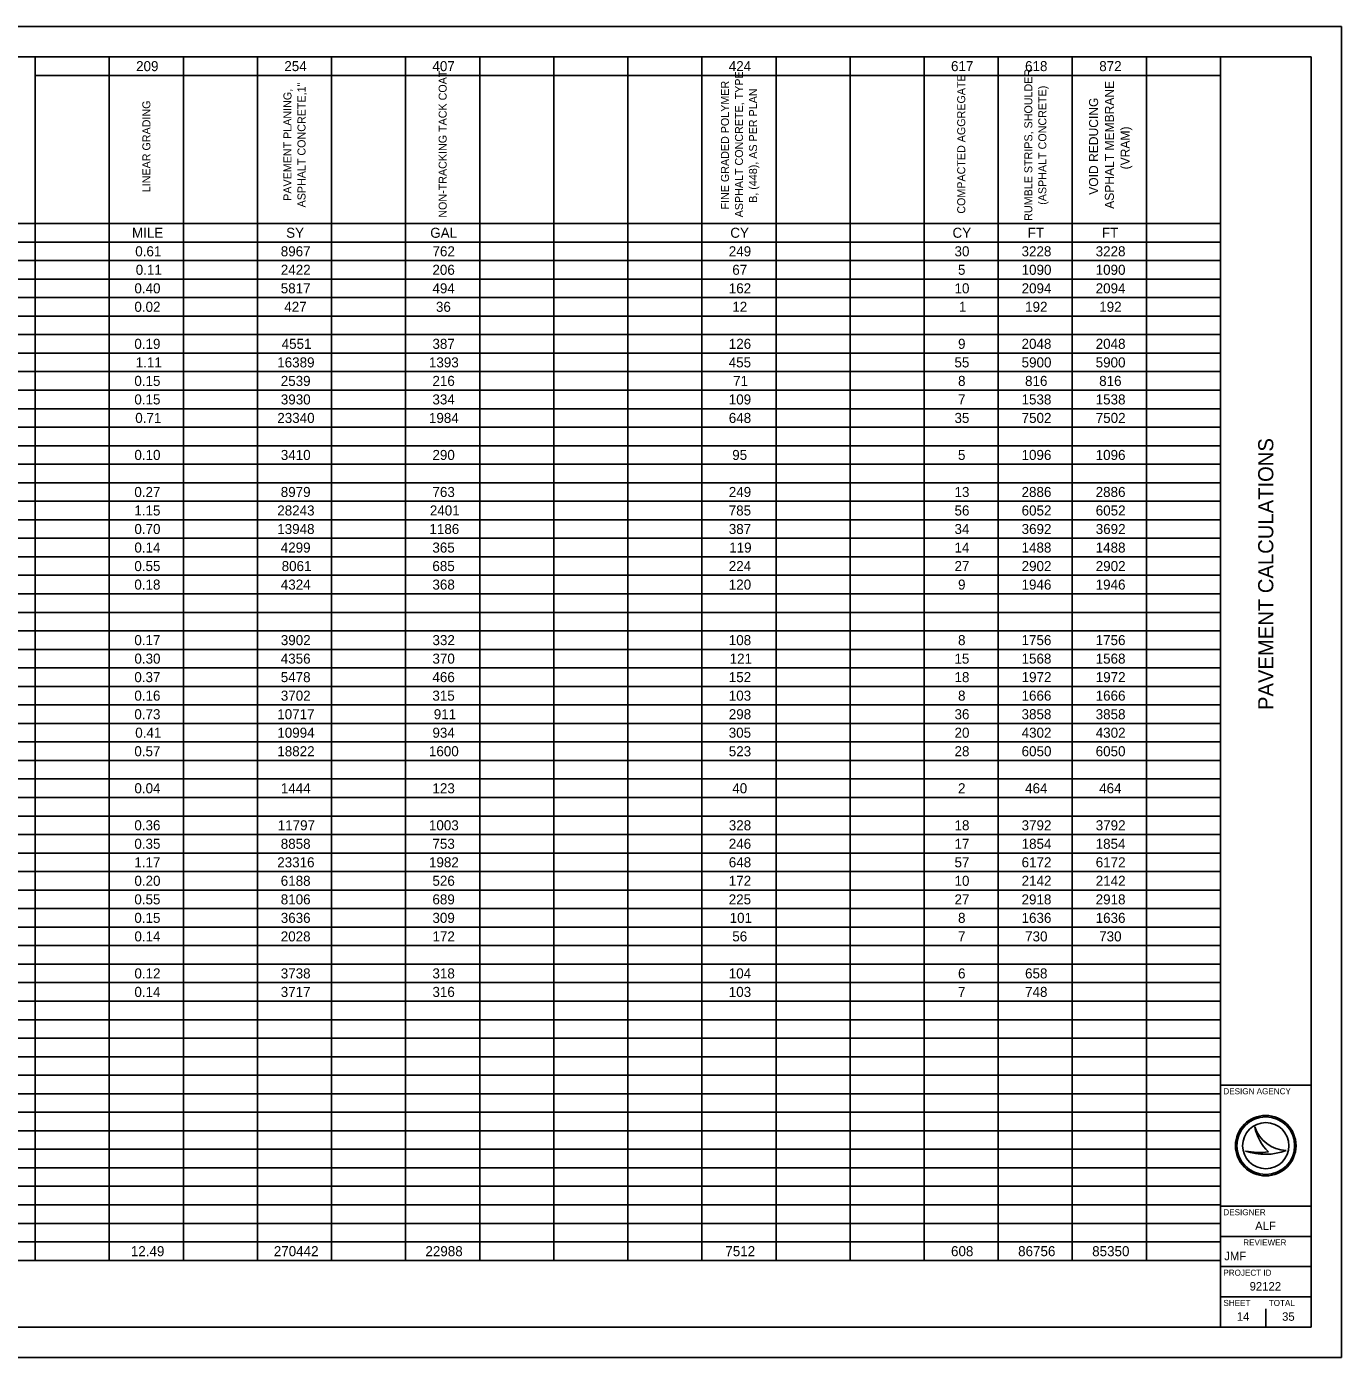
# Model space of a CAD drawing. Extents: x 0 to 34, y 0 to 22.
# Drawn here: x 12.27 to 34, y 0 to 22 of the extents above; entities that cross this region are included whole.
import ezdxf

# ---------------------------------------------------------------- set-up
doc = ezdxf.new("R2010")
doc.units = 0
for name, color, linetype in [('Default', 7, 'Continuous'), ('SH_Border', 7, 'Continuous'), ('SH_Cut_Line', 7, 'Continuous'), ('SH_Data', 7, 'Continuous')]:
    doc.layers.add(name, color=color, linetype=linetype)

msp = doc.modelspace()

# ---------------------------------------------------------------- linework, layer by layer
at = {"layer": 'Default'}
for p, q in [((1.5, 21.5), (32.002, 21.5)), ((12.412, 21.5), (12.412, 1.603)), ((13.636, 21.5), (13.636, 1.603)), ((14.861, 21.5), (14.861, 1.603)), ((16.085, 21.5), (16.085, 1.603)), ((17.309, 21.5), (17.309, 1.603)), ((18.534, 21.5), (18.534, 1.603)), ((19.758, 21.5), (19.758, 1.603)), ((20.983, 21.5), (20.983, 1.603)), ((22.207, 21.5), (22.207, 1.603)), ((23.431, 21.5), (23.431, 1.603)), ((24.656, 21.5), (24.656, 1.603)), ((25.88, 21.5), (25.88, 1.603)), ((27.105, 21.5), (27.105, 1.603)), ((28.329, 21.5), (28.329, 1.603)), ((29.553, 21.5), (29.553, 1.603)), ((30.778, 21.5), (30.778, 1.603)), ((32.002, 21.5), (32.002, 1.603)), ((12.412, 21.194), (32.002, 21.194)), ((7.514, 18.745), (32.002, 18.745)), ((1.5, 18.439), (32.002, 18.439)), ((1.5, 18.133), (32.002, 18.133)), ((1.5, 17.827), (32.002, 17.827)), ((1.5, 17.521), (32.002, 17.521)), ((1.5, 17.215), (32.002, 17.215)), ((1.5, 16.908), (32.002, 16.908)), ((1.5, 16.602), (32.002, 16.602)), ((1.5, 16.296), (32.002, 16.296)), ((1.5, 15.99), (32.002, 15.99)), ((1.5, 15.684), (32.002, 15.684)), ((1.5, 15.378), (32.002, 15.378)), ((1.5, 15.072), (32.002, 15.072)), ((1.5, 14.766), (32.002, 14.766)), ((1.5, 14.46), (32.002, 14.46)), ((1.5, 14.154), (32.002, 14.154)), ((1.5, 13.847), (32.002, 13.847)), ((1.5, 13.541), (32.002, 13.541)), ((1.5, 13.235), (32.002, 13.235)), ((1.5, 12.929), (32.002, 12.929)), ((1.5, 12.623), (32.002, 12.623)), ((1.5, 12.317), (32.002, 12.317)), ((1.5, 12.011), (32.002, 12.011)), ((1.5, 11.705), (32.002, 11.705)), ((1.5, 11.399), (32.002, 11.399)), ((1.5, 11.092), (32.002, 11.092)), ((1.5, 10.786), (32.002, 10.786)), ((1.5, 10.48), (32.002, 10.48)), ((1.5, 10.174), (32.002, 10.174)), ((1.5, 9.868), (32.002, 9.868)), ((1.5, 9.562), (32.002, 9.562)), ((1.5, 9.256), (32.002, 9.256)), ((1.5, 8.95), (32.002, 8.95)), ((1.5, 8.644), (32.002, 8.644)), ((1.5, 8.338), (32.002, 8.338)), ((1.5, 8.031), (32.002, 8.031)), ((1.5, 7.725), (32.002, 7.725)), ((1.5, 7.419), (32.002, 7.419)), ((1.5, 7.113), (32.002, 7.113)), ((1.5, 6.807), (32.002, 6.807)), ((1.5, 6.501), (32.002, 6.501)), ((1.5, 6.195), (32.002, 6.195)), ((1.5, 5.889), (32.002, 5.889)), ((1.5, 5.583), (32.002, 5.583)), ((1.5, 5.277), (32.002, 5.277)), ((1.5, 4.97), (32.002, 4.97)), ((1.5, 4.664), (32.002, 4.664)), ((1.5, 4.358), (32.002, 4.358)), ((1.5, 4.052), (32.002, 4.052)), ((1.5, 3.746), (32.002, 3.746)), ((1.5, 3.44), (32.002, 3.44)), ((1.5, 3.134), (32.002, 3.134)), ((1.5, 2.828), (32.002, 2.828)), ((1.5, 2.522), (32.002, 2.522)), ((1.5, 2.215), (32.002, 2.215)), ((1.5, 1.909), (32.002, 1.909)), ((1.5, 1.603), (32.002, 1.603))]:
    msp.add_line(p, q, dxfattribs=at)
at = {"layer": 'SH_Border'}
for p, q in [((32, 0.5), (32, 21.5)), ((32, 4.5), (33.5, 4.5)), ((32, 2.5), (33.5, 2.5)), ((32, 2), (33.5, 2)), ((32, 1.5), (33.5, 1.5)), ((32, 1), (33.5, 1))]:
    msp.add_line(p, q, dxfattribs=at)
msp.add_lwpolyline([(1.5, 21.5), (33.5, 21.5), (33.5, 0.5), (1.5, 0.5)], close=True, dxfattribs=at)
at = {"layer": 'SH_Cut_Line'}
msp.add_lwpolyline([(0, 0), (34, 0), (34, 22), (0, 22)], close=True, dxfattribs=at)
at = {"layer": 'SH_Data'}
for p, q in [((32.567, 3.81), (32.567, 3.81)), ((32.417, 3.41), (32.417, 3.41)), ((32.75, 3.5), (32.75, 3.5)), ((33.087, 3.419), (33.087, 3.419)), ((32.375, 0.675), (32.375, 0.675)), ((32.75, 0.5), (32.75, 0.8))]:
    msp.add_line(p, q, dxfattribs=at)
for radius in [0.5, 0.477, 0.477, 0.382]:
    msp.add_circle((32.75, 3.5), radius, dxfattribs=at)
for centre, radius, start, end in [((33.116, 3.998), 0.58, 198.9257, 198.9319), ((33.347, 3.97), 0.796, 191.6379, 191.6421), ((33.116, 3.998), 0.58, 198.9319, 267.1657), ((33.347, 3.97), 0.796, 191.6421, 226.0947), ((32.739, 4.37), 1.013, 251.4576, 290.0832), ((32.648, 4.654), 1.266, 259.4964, 259.4995), ((32.739, 4.37), 1.013, 251.4527, 251.4576), ((32.648, 4.654), 1.266, 259.4995, 276.6672)]:
    msp.add_arc(centre, radius, start, end, dxfattribs=at)

# ---------------------------------------------------------------- texts
at = {"layer": 'Default'}
for s, height, p in [('209', 0.1657, (14.079, 21.264)), ('254', 0.1657, (16.529, 21.264)), ('407', 0.1657, (18.977, 21.264)), ('424', 0.1657, (23.875, 21.264)), ('617', 0.1657, (27.548, 21.264)), ('618', 0.1657, (28.772, 21.264)), ('872', 0.1657, (29.998, 21.264)), ('MILE', 0.1657, (14.011, 18.509)), ('SY', 0.1657, (16.559, 18.509)), ('GAL', 0.1657, (18.941, 18.509)), ('CY', 0.1657, (23.9, 18.509)), ('CY', 0.1657, (27.573, 18.509)), ('FT', 0.1657, (28.816, 18.509)), ('FT', 0.1657, (30.041, 18.509)), ('0.61', 0.1657, (14.065, 18.203)), ('8967', 0.1657, (16.47, 18.203)), ('762', 0.1657, (18.978, 18.203)), ('249', 0.1657, (23.875, 18.203)), ('30', 0.1657, (27.606, 18.203)), ('3228', 0.1657, (28.714, 18.203)), ('3228', 0.1657, (29.939, 18.203)), ('0.11', 0.1657, (14.073, 17.897)), ('2422', 0.1657, (16.471, 17.897)), ('206', 0.1657, (18.977, 17.897)), ('67', 0.1657, (23.933, 17.897)), ('5', 0.166, (27.663, 17.897)), ('1090', 0.1657, (28.715, 17.897)), ('1090', 0.1657, (29.939, 17.897)), ('0.40', 0.1657, (14.051, 17.591)), ('5817', 0.1657, (16.47, 17.591)), ('494', 0.1657, (18.977, 17.591)), ('162', 0.1657, (23.875, 17.591)), ('10', 0.1657, (27.606, 17.591)), ('2094', 0.1657, (28.715, 17.591)), ('2094', 0.1657, (29.939, 17.591)), ('0.02', 0.1657, (14.051, 17.285)), ('427', 0.1657, (16.528, 17.285)), ('36', 0.1657, (19.035, 17.285)), ('12', 0.1657, (23.933, 17.285)), ('1', 0.166, (27.678, 17.285)), ('192', 0.1657, (28.773, 17.285)), ('192', 0.1657, (29.998, 17.285)), ('0.19', 0.1657, (14.05, 16.673)), ('4551', 0.1657, (16.485, 16.673)), ('387', 0.1657, (18.977, 16.673)), ('126', 0.1657, (23.875, 16.673)), ('9', 0.166, (27.664, 16.673)), ('2048', 0.1657, (28.714, 16.673)), ('2048', 0.1657, (29.939, 16.673)), ('1.11', 0.1657, (14.073, 16.366)), ('16389', 0.1657, (16.412, 16.366)), ('1393', 0.1657, (18.919, 16.366)), ('455', 0.1657, (23.874, 16.366)), ('55', 0.1657, (27.605, 16.366)), ('5900', 0.1657, (28.715, 16.366)), ('5900', 0.1657, (29.939, 16.366)), ('0.15', 0.1657, (14.05, 16.06)), ('2539', 0.1657, (16.47, 16.06)), ('216', 0.1657, (18.977, 16.06)), ('71', 0.1657, (23.947, 16.06)), ('8', 0.166, (27.664, 16.06)), ('816', 0.1657, (28.772, 16.06)), ('816', 0.1657, (29.997, 16.06)), ('0.15', 0.1657, (14.05, 15.754)), ('3930', 0.1657, (16.471, 15.754)), ('334', 0.1657, (18.977, 15.754)), ('109', 0.1657, (23.875, 15.754)), ('7', 0.166, (27.664, 15.754)), ('1538', 0.1657, (28.714, 15.754)), ('1538', 0.1657, (29.939, 15.754)), ('0.71', 0.1657, (14.065, 15.448)), ('23340', 0.1657, (16.413, 15.448)), ('1984', 0.1657, (18.919, 15.448)), ('648', 0.1657, (23.875, 15.448)), ('35', 0.1657, (27.605, 15.448)), ('7502', 0.1657, (28.715, 15.448)), ('7502', 0.1657, (29.94, 15.448)), ('0.10', 0.1657, (14.051, 14.836)), ('3410', 0.1657, (16.471, 14.836)), ('290', 0.1657, (18.977, 14.836)), ('95', 0.1657, (23.932, 14.836)), ('5', 0.166, (27.663, 14.836)), ('1096', 0.1657, (28.714, 14.836)), ('1096', 0.1657, (29.939, 14.836)), ('0.27', 0.1657, (14.05, 14.224)), ('8979', 0.1657, (16.47, 14.224)), ('763', 0.1657, (18.977, 14.224)), ('249', 0.1657, (23.875, 14.224)), ('13', 0.1657, (27.606, 14.224)), ('2886', 0.1657, (28.714, 14.224)), ('2886', 0.1657, (29.939, 14.224)), ('1.15', 0.1657, (14.05, 13.918)), ('28243', 0.1657, (16.412, 13.918)), ('2401', 0.1657, (18.934, 13.918)), ('785', 0.1657, (23.874, 13.918)), ('56', 0.1657, (27.606, 13.918)), ('6052', 0.1657, (28.715, 13.918)), ('6052', 0.1657, (29.94, 13.918)), ('0.70', 0.1657, (14.051, 13.612)), ('13948', 0.1657, (16.412, 13.612)), ('1186', 0.1657, (18.927, 13.612)), ('387', 0.1657, (23.875, 13.612)), ('34', 0.1657, (27.606, 13.612)), ('3692', 0.1657, (28.715, 13.612)), ('3692', 0.1657, (29.94, 13.612)), ('0.14', 0.1657, (14.051, 13.305)), ('4299', 0.1657, (16.47, 13.305)), ('365', 0.1657, (18.976, 13.305)), ('119', 0.1657, (23.882, 13.305)), ('14', 0.1657, (27.606, 13.305)), ('1488', 0.1657, (28.714, 13.305)), ('1488', 0.1657, (29.939, 13.305)), ('0.55', 0.1657, (14.05, 12.999)), ('8061', 0.1657, (16.485, 12.999)), ('685', 0.1657, (18.976, 12.999)), ('224', 0.1657, (23.875, 12.999)), ('27', 0.1657, (27.606, 12.999)), ('2902', 0.1657, (28.715, 12.999)), ('2902', 0.1657, (29.94, 12.999)), ('0.18', 0.1657, (14.05, 12.693)), ('4324', 0.1657, (16.471, 12.693)), ('368', 0.1657, (18.977, 12.693)), ('120', 0.1657, (23.875, 12.693)), ('9', 0.166, (27.664, 12.693)), ('1946', 0.1657, (28.714, 12.693)), ('1946', 0.1657, (29.939, 12.693)), ('0.17', 0.1657, (14.05, 11.775)), ('3902', 0.1657, (16.471, 11.775)), ('332', 0.1657, (18.978, 11.775)), ('108', 0.1657, (23.875, 11.775)), ('8', 0.166, (27.664, 11.775)), ('1756', 0.1657, (28.714, 11.775)), ('1756', 0.1657, (29.939, 11.775)), ('0.30', 0.1657, (14.051, 11.469)), ('4356', 0.1657, (16.47, 11.469)), ('370', 0.1657, (18.977, 11.469)), ('121', 0.1657, (23.889, 11.469)), ('15', 0.1657, (27.605, 11.469)), ('1568', 0.1657, (28.714, 11.469)), ('1568', 0.1657, (29.939, 11.469)), ('0.37', 0.1657, (14.05, 11.163)), ('5478', 0.1657, (16.47, 11.163)), ('466', 0.1657, (18.977, 11.163)), ('152', 0.1657, (23.875, 11.163)), ('18', 0.1657, (27.606, 11.163)), ('1972', 0.1657, (28.715, 11.163)), ('1972', 0.1657, (29.94, 11.163)), ('0.16', 0.1657, (14.05, 10.857)), ('3702', 0.1657, (16.471, 10.857)), ('315', 0.1657, (18.976, 10.857)), ('103', 0.1657, (23.875, 10.857)), ('8', 0.166, (27.664, 10.857)), ('1666', 0.1657, (28.714, 10.857)), ('1666', 0.1657, (29.939, 10.857)), ('0.73', 0.1657, (14.05, 10.55)), ('10717', 0.1657, (16.412, 10.55)), ('911', 0.1657, (18.999, 10.55)), ('298', 0.1657, (23.875, 10.55)), ('36', 0.1657, (27.606, 10.55)), ('3858', 0.1657, (28.714, 10.55)), ('3858', 0.1657, (29.939, 10.55)), ('0.41', 0.1657, (14.065, 10.244)), ('10994', 0.1657, (16.413, 10.244)), ('934', 0.1657, (18.977, 10.244)), ('305', 0.1657, (23.874, 10.244)), ('20', 0.1657, (27.606, 10.244)), ('4302', 0.1657, (28.715, 10.244)), ('4302', 0.1657, (29.94, 10.244)), ('0.57', 0.1657, (14.05, 9.938)), ('18822', 0.1657, (16.413, 9.938)), ('1600', 0.1657, (18.919, 9.938)), ('523', 0.1657, (23.875, 9.938)), ('28', 0.1657, (27.606, 9.938)), ('6050', 0.1657, (28.715, 9.938)), ('6050', 0.1657, (29.939, 9.938)), ('0.04', 0.1657, (14.051, 9.326)), ('1444', 0.1657, (16.471, 9.326)), ('123', 0.1657, (18.977, 9.326)), ('40', 0.1657, (23.933, 9.326)), ('2', 0.166, (27.664, 9.326)), ('464', 0.1657, (28.773, 9.326)), ('464', 0.1657, (29.997, 9.326)), ('0.36', 0.1657, (14.05, 8.714)), ('11797', 0.1657, (16.42, 8.714)), ('1003', 0.1657, (18.919, 8.714)), ('328', 0.1657, (23.875, 8.714)), ('18', 0.1657, (27.606, 8.714)), ('3792', 0.1657, (28.715, 8.714)), ('3792', 0.1657, (29.94, 8.714)), ('0.35', 0.1657, (14.05, 8.408)), ('8858', 0.1657, (16.47, 8.408)), ('753', 0.1657, (18.977, 8.408)), ('246', 0.1657, (23.875, 8.408)), ('17', 0.1657, (27.606, 8.408)), ('1854', 0.1657, (28.715, 8.408)), ('1854', 0.1657, (29.939, 8.408)), ('1.17', 0.1657, (14.05, 8.102)), ('23316', 0.1657, (16.412, 8.102)), ('1982', 0.1657, (18.92, 8.102)), ('648', 0.1657, (23.875, 8.102)), ('57', 0.1657, (27.606, 8.102)), ('6172', 0.1657, (28.715, 8.102)), ('6172', 0.1657, (29.94, 8.102)), ('0.20', 0.1657, (14.051, 7.796)), ('6188', 0.1657, (16.47, 7.796)), ('526', 0.1657, (18.977, 7.796)), ('172', 0.1657, (23.875, 7.796)), ('10', 0.1657, (27.606, 7.796)), ('2142', 0.1657, (28.715, 7.796)), ('2142', 0.1657, (29.94, 7.796)), ('0.55', 0.1657, (14.05, 7.489)), ('8106', 0.1657, (16.47, 7.489)), ('689', 0.1657, (18.977, 7.489)), ('225', 0.1657, (23.874, 7.489)), ('27', 0.1657, (27.606, 7.489)), ('2918', 0.1657, (28.714, 7.489)), ('2918', 0.1657, (29.939, 7.489)), ('0.15', 0.1657, (14.05, 7.183)), ('3636', 0.1657, (16.47, 7.183)), ('309', 0.1657, (18.977, 7.183)), ('101', 0.1657, (23.889, 7.183)), ('8', 0.166, (27.664, 7.183)), ('1636', 0.1657, (28.714, 7.183)), ('1636', 0.1657, (29.939, 7.183)), ('0.14', 0.1657, (14.051, 6.877)), ('2028', 0.1657, (16.47, 6.877)), ('172', 0.1657, (18.978, 6.877)), ('56', 0.1657, (23.933, 6.877)), ('7', 0.166, (27.664, 6.877)), ('730', 0.1657, (28.773, 6.877)), ('730', 0.1657, (29.997, 6.877)), ('0.12', 0.1657, (14.051, 6.265)), ('3738', 0.1657, (16.47, 6.265)), ('318', 0.1657, (18.977, 6.265)), ('104', 0.1657, (23.875, 6.265)), ('6', 0.166, (27.664, 6.265)), ('658', 0.1657, (28.772, 6.265)), ('0.14', 0.1657, (14.051, 5.959)), ('3717', 0.1657, (16.47, 5.959)), ('316', 0.1657, (18.977, 5.959)), ('103', 0.1657, (23.875, 5.959)), ('7', 0.166, (27.664, 5.959)), ('748', 0.1657, (28.772, 5.959)), ('12.49', 0.1657, (13.992, 1.673)), ('270442', 0.1657, (16.355, 1.673)), ('22988', 0.1657, (18.861, 1.673)), ('7512', 0.1657, (23.818, 1.673)), ('608', 0.1657, (27.548, 1.673)), ('86756', 0.1657, (28.657, 1.673)), ('85350', 0.1657, (29.881, 1.673))]:
    msp.add_text(s, height=height, dxfattribs=at).set_placement(p)
for s, height, p in [('NON-TRACKING TACK COAT', 0.13252, (19.212, 18.841)), ('ASPHALT CONCRETE, TYPE ', 0.13252, (24.11, 18.847)), ('COMPACTED AGGREGATE', 0.13252, (27.783, 18.907)), ('RUMBLE STRIPS, SHOULDER ', 0.13252, (28.892, 18.79)), ('PAVEMENT PLANING, ', 0.13252, (16.647, 19.12)), ('ASPHALT CONCRETE,1"', 0.13252, (16.879, 19.011)), ('FINE GRADED POLYMER ', 0.13252, (23.878, 18.977)), ('B, (448), AS PER PLAN', 0.13252, (24.342, 19.087)), ('(ASPHALT CONCRETE)', 0.13252, (29.124, 19.054)), ('ASPHALT MEMBRANE ', 0.14909, (30.24, 18.988)), ('LINEAR GRADING', 0.13252, (14.315, 19.262)), ('VOID REDUCING ', 0.14909, (29.979, 19.22)), ('(VRAM)', 0.1491, (30.501, 19.64))]:
    msp.add_text(s, height=height, rotation=90, dxfattribs=at).set_placement(p)
at = {"layer": 'SH_Data'}
msp.add_text('PAVEMENT CALCULATIONS', height=0.25, rotation=90, dxfattribs=at).set_placement((32.875, 10.702))
for s, height, p in [('DESIGN AGENCY', 0.1, (32.05, 4.35)), ('DESIGNER', 0.1, (32.05, 2.35)), ('ALF', 0.14, (32.575, 2.105)), ('REVIEWER', 0.1, (32.378, 1.85)), ('JMF', 0.14, (32.064, 1.605)), ('PROJECT ID', 0.1, (32.05, 1.35)), ('92122', 0.14, (32.483, 1.105)), ('SHEET', 0.1, (32.05, 0.85)), ('TOTAL', 0.1, (32.8, 0.85)), ('14', 0.14, (32.271, 0.605)), ('35', 0.14, (33.02, 0.605))]:
    msp.add_text(s, height=height, dxfattribs=at).set_placement(p)

doc.saveas('drawing.dxf')
